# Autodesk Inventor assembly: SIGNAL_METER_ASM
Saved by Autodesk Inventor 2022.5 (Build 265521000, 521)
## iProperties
Created: 2024-11
Part Number: SIGNAL_METER_ASM
Document SubType Name: Assembly
Designer: AdminForWorker
Title: Signal_Meter_V4_for-3D v2
Author: AdminForWorker
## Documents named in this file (4)
- c:\worker\convert-fusion-r05-cosv3\tmp\job-1\25\temp\files\0fb0f5f3-35f0-4640-a443-70722ffa1432\b991013a-2983-43b8-b932-047d13b6720f.iam
- c:\worker\convert-fusion-r05-cosv3\tmp\job-1\25\temp\files\0fb0f5f3-35f0-4640-a443-70722ffa1432\RAKU73020147.ipt
- c:\worker\convert-fusion-r05-cosv3\tmp\job-1\25\temp\files\0fb0f5f3-35f0-4640-a443-70722ffa1432\RAKU73020148.ipt
- c:\worker\convert-fusion-r05-cosv3\tmp\job-1\25\temp\files\0fb0f5f3-35f0-4640-a443-70722ffa1432\CAP.ipt
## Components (3 placed, 3 different names)
1. RAKU73020147:1
2. RAKU73020148:1
3. CAP:1
